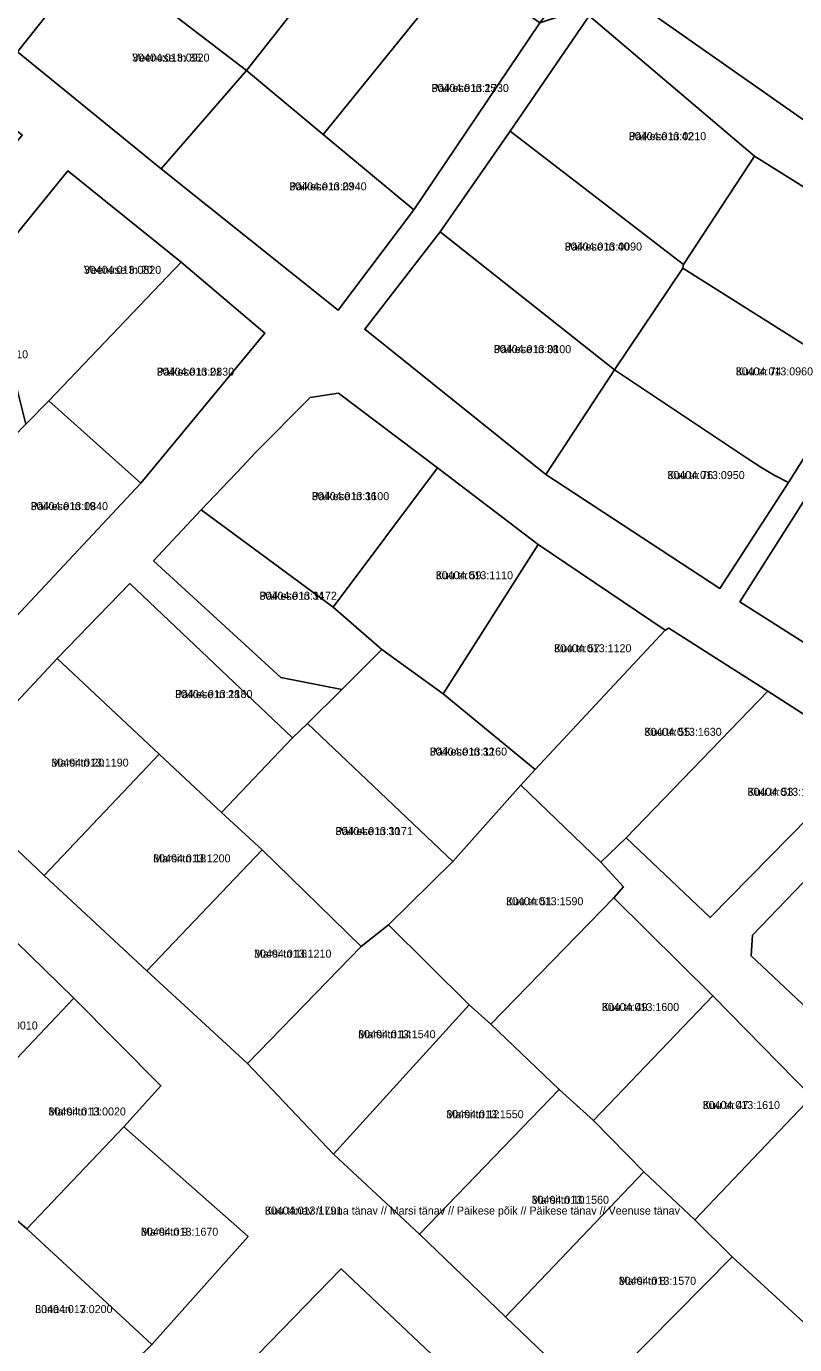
# Model space of a CAD drawing. Extents: x 542681 to 554572, y 6566489 to 6580482.
# Drawn here: x 543809.9 to 543954, y 6575908.9 to 6576155.9 of the extents above; entities that cross this region are included whole.
import ezdxf

# ---------------------------------------------------------------- set-up
doc = ezdxf.new("R2010")
doc.units = 0
for name, color, linetype in [('L_AADRESS', 7, 'Continuous'), ('PIIR', 7, 'Continuous'), ('TUNNUS', 7, 'Continuous')]:
    doc.layers.add(name, color=color, linetype=linetype)

msp = doc.modelspace()

# ---------------------------------------------------------------- linework, layer by layer
at = {"layer": 'PIIR'}
for points in [[(543980.11, 6576110.56), (543946.49, 6576131.63), (543915.46, 6576157.88), (543914.05, 6576159.16), (543906.21, 6576156.61), (543910.47, 6576162.14), (543881.73, 6576185.54), (543881.07, 6576184.76), (543850, 6576209.33), (543835.6, 6576221.08), (543841.35, 6576227.09), (543856.53, 6576214.44), (543906.78, 6576172.72), (543984.31, 6576118.38)], [(543822.78, 6576169.45), (543808.25, 6576151.17), (543835.23, 6576129.22), (543868.39, 6576102.74), (543882.6, 6576121.55), (543906.21, 6576156.61)], [(543915.46, 6576157.88), (543900.63, 6576136.29), (543887.55, 6576117.44), (543873.38, 6576099.17), (543907.34, 6576071.96), (543939.99, 6576050.62), (543952.86, 6576070.45), (543964.98, 6576089.69)], [(543957.22, 6575955.33), (543938.64, 6575974.25), (543920.07, 6575992.62), (543921.9, 6575994.67), (543917.67, 6575999.29), (543922.41, 6576003.9), (543938.16, 6575988.94), (543967.93, 6576019.18), (543948.95, 6576031.34), (543930.41, 6576043.18), (543929.72, 6576042.76), (543905.93, 6576058.83), (543887, 6576073.21), (543868.47, 6576087.2), (543863.16, 6576086.41), (543852.85, 6576075.99), (543850.51, 6576073.54), (543842.74, 6576065.31), (543833.78, 6576055.81), (543857.68, 6576033.9), (543869.07, 6576031.68), (543862.64, 6576025.29), (543859.87, 6576022.6), (543829.35, 6576051.52), (543815.74, 6576037.46), (543794.38, 6576014.66), (543813.28, 6575996.79), (543832.54, 6575978.94), (543851.4, 6575961.56), (543867.5, 6575944.61), (543883.64, 6575929.58), (543899.76, 6575914.09), (543915.9, 6575898.68)], [(543956.32, 6576067.94), (543943.74, 6576048.11), (543975.77, 6576027.72)], [(543974.47, 6576015.13), (543946.1, 6575985.66), (543945.84, 6575981.74), (543960.64, 6575967.84)], [(543817.99, 6575893.76), (543833.47, 6575908.92), (543851.52, 6575929.2), (543828.19, 6575949.71), (543835.15, 6575957.43), (543818.86, 6575973.81), (543802.52, 6575989.67), (543786.1, 6576005.7), (543759.8, 6575978.44), (543740.1, 6575957.98), (543763.79, 6575936.08), (543760.88, 6575932.83), (543757.91, 6575929.5), (543759.79, 6575927.48), (543757.61, 6575925.06), (543754.02, 6575928.65), (543752.98, 6575935.65), (543735.8, 6575953.58), (543716.35, 6575933.28), (543699.76, 6575916.06), (543725.6, 6575892.69)], [(543885.82, 6575907.18), (543868.95, 6575923.09), (543844.46, 6575897.96)]]:
    msp.add_lwpolyline(points, dxfattribs=at)
for points in [[(543939.43, 6576208.34), (543951.32, 6576196.79), (543973.39, 6576176.45), (543996.3, 6576200.53), (544043.16, 6576166.01), (544009.15, 6576119.22), (543984.31, 6576118.38), (543906.78, 6576172.72)], [(543837.56, 6576188.04), (543865.8, 6576166.2), (543851.24, 6576147.66), (543822.78, 6576169.45)], [(543881.07, 6576184.76), (543881.73, 6576185.54), (543910.47, 6576162.14), (543906.21, 6576156.61), (543898.67, 6576161.98), (543889.37, 6576160.99), (543887.26, 6576162.45), (543865.62, 6576135.66), (543851.24, 6576147.66), (543865.8, 6576166.2)], [(543822.78, 6576169.45), (543851.24, 6576147.66), (543835.23, 6576129.22), (543808.25, 6576151.17)], [(543887.26, 6576162.45), (543889.37, 6576160.99), (543898.67, 6576161.98), (543906.21, 6576156.61), (543882.6, 6576121.55), (543865.62, 6576135.66)], [(543766.21, 6576035.75), (543783.28, 6576019.27), (543807.09, 6576044.34), (543831.37, 6576070.35), (543854.66, 6576098.47), (543838.99, 6576111.77), (543817.71, 6576128.87), (543805.64, 6576113.98), (543798.71, 6576122.83), (543809.17, 6576135.55), (543784.05, 6576155.57), (543773.55, 6576144.6), (543745.39, 6576112.95), (543739.29, 6576103.11), (543737.19, 6576101.39), (543724.96, 6576087.63), (543724.78, 6576085.78), (543731.95, 6576077.1), (543737.32, 6576071.97), (543749.35, 6576062.98), (543752.7, 6576059.07), (543759.22, 6576045.22), (543761.85, 6576042.29)], [(543915.46, 6576157.88), (543946.49, 6576131.63), (543933.19, 6576111.32), (543900.63, 6576136.29)], [(543851.24, 6576147.66), (543865.62, 6576135.66), (543882.6, 6576121.55), (543868.39, 6576102.74), (543835.23, 6576129.22)], [(543900.63, 6576136.29), (543933.19, 6576111.32), (543933.01, 6576110.61), (543920.19, 6576091.57), (543887.55, 6576117.44)], [(543980.11, 6576110.56), (543968.11, 6576091.17), (543964.98, 6576089.69), (543962.96, 6576091.73), (543933.01, 6576110.61), (543933.19, 6576111.32), (543946.49, 6576131.63)], [(543809.84, 6576081.36), (543802.45, 6576110.65), (543805.64, 6576113.98), (543817.71, 6576128.87), (543838.99, 6576111.77), (543814.12, 6576085.76)], [(543887.55, 6576117.44), (543920.19, 6576091.57), (543907.34, 6576071.96), (543873.38, 6576099.17)], [(543838.99, 6576111.77), (543854.66, 6576098.47), (543831.37, 6576070.35), (543814.12, 6576085.76)], [(543920.19, 6576091.57), (543933.01, 6576110.61), (543962.96, 6576091.73), (543964.98, 6576089.69), (543952.86, 6576070.45), (543950.15, 6576071.84), (543947.68, 6576073.32), (543945.36, 6576074.84)], [(543920.19, 6576091.57), (543945.36, 6576074.84), (543947.68, 6576073.32), (543950.15, 6576071.84), (543952.86, 6576070.45), (543939.99, 6576050.62), (543907.34, 6576071.96)], [(543850.51, 6576073.54), (543852.85, 6576075.99), (543863.16, 6576086.41), (543868.47, 6576087.2), (543887, 6576073.21), (543867.45, 6576047.1), (543842.74, 6576065.31)], [(543795.79, 6576067.01), (543809.84, 6576081.36), (543814.12, 6576085.76), (543831.37, 6576070.35), (543807.09, 6576044.35), (543790.12, 6576060.74)], [(543867.45, 6576047.1), (543887, 6576073.21), (543905.93, 6576058.83), (543888.07, 6576030.86), (543876.62, 6576039.18)], [(543943.74, 6576048.11), (543956.32, 6576067.94), (543988.63, 6576047.94), (543975.77, 6576027.72)], [(543867.45, 6576047.1), (543876.62, 6576039.18), (543869.07, 6576031.68), (543857.68, 6576033.9), (543833.78, 6576055.81), (543842.74, 6576065.31)], [(543905.37, 6576016.69), (543888.07, 6576030.86), (543905.93, 6576058.83), (543929.72, 6576042.76)], [(543834.84, 6576019.56), (543815.74, 6576037.46), (543829.35, 6576051.52), (543859.87, 6576022.6), (543846.54, 6576008.6)], [(543922.41, 6576003.9), (543917.67, 6575999.29), (543902.67, 6576013.75), (543905.37, 6576016.69), (543929.72, 6576042.76), (543930.41, 6576043.18), (543948.95, 6576031.34)], [(543794.38, 6576014.66), (543815.74, 6576037.46), (543834.84, 6576019.56), (543813.28, 6575996.79)], [(543876.62, 6576039.18), (543888.07, 6576030.86), (543905.37, 6576016.69), (543902.67, 6576013.75), (543889.92, 6575999.41), (543862.64, 6576025.29), (543869.07, 6576031.68)], [(543922.41, 6576003.9), (543948.95, 6576031.34), (543967.93, 6576019.18), (543938.16, 6575988.94)], [(543889.92, 6575999.41), (543877.87, 6575987.59), (543872.73, 6575983.49), (543854.16, 6576001.61), (543846.54, 6576008.6), (543859.87, 6576022.6), (543862.64, 6576025.29)], [(543834.84, 6576019.56), (543846.54, 6576008.6), (543854.16, 6576001.61), (543832.54, 6575978.94), (543813.28, 6575996.79)], [(543945.84, 6575981.74), (543946.1, 6575985.66), (543974.47, 6576015.13), (543994.39, 6576003.01), (543960.64, 6575967.84)], [(543892.94, 6575972.57), (543877.87, 6575987.59), (543889.92, 6575999.41), (543902.67, 6576013.75), (543917.67, 6575999.29), (543921.9, 6575994.67), (543920.07, 6575992.62), (543897.04, 6575968.94)], [(543832.54, 6575978.94), (543854.16, 6576001.61), (543872.73, 6575983.49), (543851.4, 6575961.56)], [(543909.85, 6575956.72), (543897.04, 6575968.94), (543920.07, 6575992.62), (543938.64, 6575974.25), (543916.27, 6575950.88)], [(543785.17, 6575953.9), (543776.26, 6575962.52), (543802.52, 6575989.67), (543818.86, 6575973.81), (543793.03, 6575946.6)], [(543851.4, 6575961.56), (543872.73, 6575983.49), (543877.87, 6575987.59), (543892.94, 6575972.57), (543867.5, 6575944.61)], [(543803.81, 6575935.87), (543793.03, 6575946.6), (543818.86, 6575973.81), (543835.15, 6575957.43), (543828.19, 6575949.71), (543810.02, 6575930.64)], [(543925.71, 6575941.32), (543916.27, 6575950.88), (543938.64, 6575974.25), (543957.22, 6575955.33), (543935.26, 6575932.29)], [(543897.04, 6575968.94), (543909.85, 6575956.72), (543883.64, 6575929.58), (543867.5, 6575944.61), (543892.94, 6575972.57)], [(543935.26, 6575932.29), (543957.22, 6575955.33), (543964.77, 6575963.44), (543981.94, 6575947.26), (543973.38, 6575930.78), (543960.23, 6575908.93), (543942.27, 6575925.34)], [(543916.27, 6575950.88), (543925.71, 6575941.32), (543899.76, 6575914.09), (543883.64, 6575929.58), (543909.85, 6575956.72)], [(543828.19, 6575949.71), (543851.52, 6575929.2), (543833.47, 6575908.92), (543810.02, 6575930.64)], [(543935.26, 6575932.29), (543942.27, 6575925.34), (543915.9, 6575898.68), (543899.76, 6575914.09), (543925.71, 6575941.32)], [(543803.81, 6575935.87), (543810.02, 6575930.64), (543833.47, 6575908.92), (543817.99, 6575893.76), (543789.72, 6575920.93)], [(543915.9, 6575898.68), (543942.27, 6575925.34), (543960.23, 6575908.93), (543956.27, 6575902.9), (543949, 6575894.77), (543945.94, 6575897.25), (543932.12, 6575883.17)], [(543844.46, 6575897.96), (543868.95, 6575923.09), (543885.82, 6575907.18), (543860.49, 6575881.7)]]:
    msp.add_lwpolyline(points, close=True, dxfattribs=at)

# ---------------------------------------------------------------- texts
at = {"layer": 'L_AADRESS'}
for s, p in [('Veenuse tn 35', (543829.78, 6576149.33)), ('Päikese tn 25', (543885.91, 6576143.63)), ('Päikese tn 42', (543922.91, 6576134.6)), ('Päikese tn 23', (543859.24, 6576125.2)), ('Päikese tn 40', (543910.88, 6576113.93)), ('Veenuse tn 20', (543820.72, 6576109.56)), ('Päikese tn 38', (543897.6, 6576094.7)), ('Päikese tn 21', (543834.39, 6576090.48)), ('Kuu tn 74', (543942.95, 6576090.53)), ('Kuu tn 76', (543930.13, 6576071.1)), ('Päikese tn 19', (543810.74, 6576065.28)), ('Päikese tn 36', (543863.47, 6576067.15)), ('Kuu tn 59', (543886.69, 6576052.33)), ('Päikese tn 34', (543853.66, 6576048.49)), ('Kuu tn 57', (543908.89, 6576038.65)), ('Päikese tn 28', (543837.82, 6576030.06)), ('Kuu tn 55', (543925.81, 6576022.99)), ('Päikese tn 32', (543885.57, 6576019.29)), ('Marsi tn 20', (543814.61, 6576017.22)), ('Kuu tn 53', (543945.17, 6576011.75)), ('Päikese tn 30', (543867.9, 6576004.39)), ('Marsi tn 18', (543833.72, 6575999.28)), ('Kuu tn 51', (543899.88, 6575991.24)), ('Marsi tn 16', (543852.63, 6575981.42)), ('Kuu tn 49', (543917.84, 6575971.42)), ('Marsi tn 14', (543872.17, 6575966.33)), ('Marsi tn 11', (543814.09, 6575951.85)), ('Kuu tn 47', (543936.75, 6575953.06)), ('Marsi tn 12', (543888.68, 6575951.34)), ('Marsi tn 10', (543904.68, 6575935.3)), ('Kuu tänav // Luna tänav // Marsi tänav // Päikese põik // Päikese tänav // Veenuse tänav', (543854.66, 6575933.28)), ('Marsi tn 9', (543831.42, 6575929.32)), ('Marsi tn 8', (543921.02, 6575920.12)), ('Luna tn 17', (543811.59, 6575914.82))]:
    msp.add_text(s, height=1.5, dxfattribs=at).set_placement(p)
at = {"layer": 'TUNNUS'}
for s, p in [('30404:013:0920', (543829.78, 6576149.33)), ('30404:013:1730', (543885.91, 6576143.63)), ('30404:013:0210', (543922.91, 6576134.6)), ('30404:013:0940', (543859.24, 6576125.2)), ('30404:013:0090', (543910.88, 6576113.93)), ('30404:013:0820', (543820.72, 6576109.56)), ('30404:013:0100', (543897.6, 6576094.7)), ('30404:013:0810', (543795.75, 6576093.73)), ('30404:013:0830', (543834.39, 6576090.48)), ('30404:013:0960', (543942.95, 6576090.53)), ('30404:013:0950', (543930.13, 6576071.1)), ('30404:013:0840', (543810.74, 6576065.28)), ('30404:013:1100', (543863.47, 6576067.15)), ('30404:013:1110', (543886.69, 6576052.33)), ('30404:013:1172', (543853.66, 6576048.49)), ('30404:013:1120', (543908.89, 6576038.65)), ('30404:013:1180', (543837.82, 6576030.06)), ('30404:013:1630', (543925.81, 6576022.99)), ('30404:013:1160', (543885.57, 6576019.29)), ('30404:013:1190', (543814.61, 6576017.22)), ('30404:013:1640', (543945.17, 6576011.75)), ('30404:013:1171', (543867.9, 6576004.39)), ('30404:013:1200', (543833.72, 6575999.28)), ('30404:013:1590', (543899.88, 6575991.24)), ('30404:013:1210', (543852.63, 6575981.42)), ('30404:013:1600', (543917.84, 6575971.42)), ('30404:013:0010', (543797.56, 6575967.96)), ('30404:013:1540', (543872.17, 6575966.33)), ('30404:013:0020', (543814.09, 6575951.85)), ('30404:013:1610', (543936.75, 6575953.06)), ('30404:013:1550', (543888.68, 6575951.34)), ('30404:013:1560', (543904.68, 6575935.3)), ('30404:013:1791', (543854.66, 6575933.28)), ('30404:013:1670', (543831.42, 6575929.32)), ('30404:013:1570', (543921.02, 6575920.12)), ('30404:013:0200', (543811.59, 6575914.82))]:
    msp.add_text(s, height=1.5, dxfattribs=at).set_placement(p)

doc.saveas('drawing.dxf')
